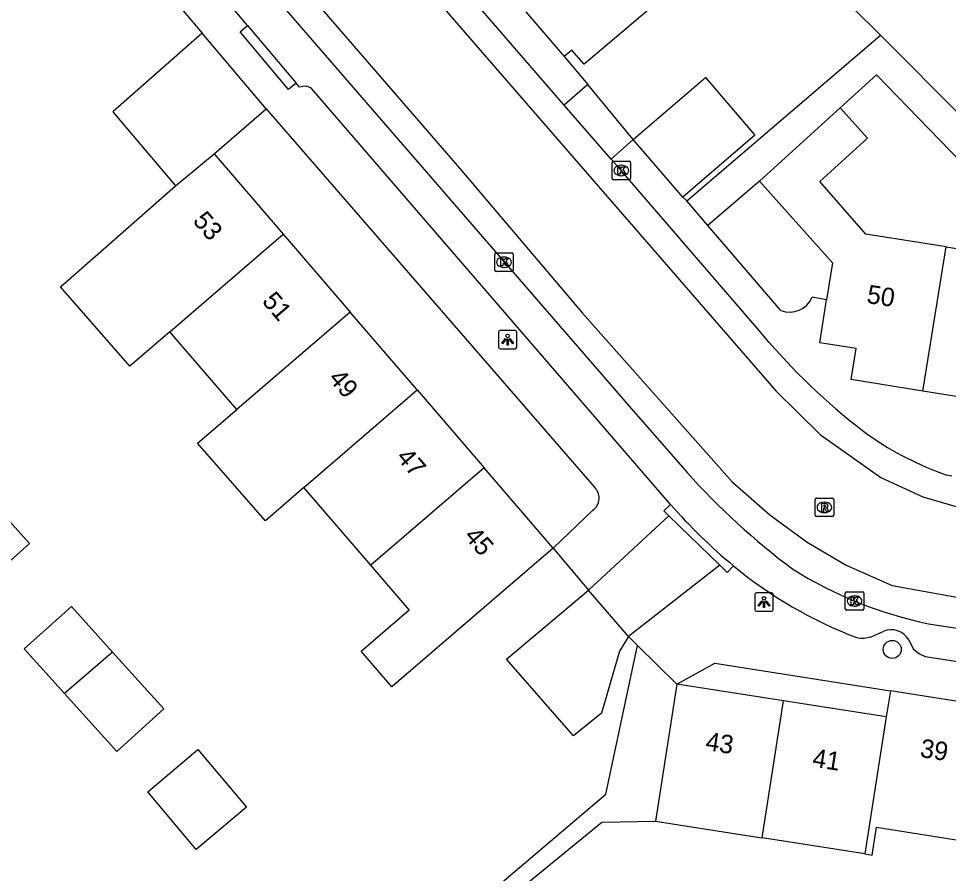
# Model space of a CAD drawing. Extents: x 162172 to 163187, y 382874 to 383684.
# Drawn here: x 162523.1 to 162573.4, y 383322.9 to 383369.1 of the extents above; entities that cross this region are included whole.
import ezdxf

# ---------------------------------------------------------------- set-up
doc = ezdxf.new("R2010")
doc.units = 0
for name, color, linetype in [('IMGEO_Boom', 7, 'Continuous'), ('IMGEO_Kolk', 7, 'Continuous'), ('IMGEO_Lichtpunt', 7, 'Continuous'), ('IMGEO_Pand', 7, 'Continuous'), ('IMGEO_Pand_nummerreeks', 7, 'Continuous'), ('IMGEO_Rijbaan_lokaal_gesloten', 7, 'Continuous'), ('IMGEO_Rijbaan_lokaal_open', 7, 'Continuous'), ('IMGEO_Rioolput', 7, 'Continuous'), ('IMGEO_Voetpad_open', 7, 'Continuous')]:
    doc.layers.add(name, color=color, linetype=linetype)

msp = doc.modelspace()

# ---------------------------------------------------------------- linework, layer by layer
at = {"layer": 'IMGEO_Boom'}
msp.add_circle((162570.37, 383334.962), 0.489, dxfattribs=at)
at = {"layer": 'IMGEO_Kolk'}
for p, q in [((162555.215, 383360.44), (162555.215, 383361.292)), ((162555.29, 383361.366), (162556.142, 383361.366)), ((162555.703, 383361.146), (162555.728, 383361.146)), ((162556.216, 383361.292), (162556.216, 383360.44)), ((162556.142, 383360.366), (162555.29, 383360.366)), ((162555.726, 383360.586), (162555.701, 383360.586)), ((162548.874, 383355.482), (162548.874, 383356.334)), ((162548.949, 383356.408), (162549.801, 383356.408)), ((162549.362, 383356.188), (162549.387, 383356.188)), ((162549.875, 383356.334), (162549.875, 383355.482)), ((162549.385, 383355.628), (162549.36, 383355.628)), ((162549.801, 383355.408), (162548.949, 383355.408)), ((162567.831, 383337.157), (162567.831, 383338.009)), ((162567.906, 383338.083), (162568.758, 383338.083)), ((162568.832, 383338.009), (162568.832, 383337.157)), ((162568.319, 383337.863), (162568.344, 383337.863)), ((162568.758, 383337.083), (162567.906, 383337.083)), ((162568.342, 383337.303), (162568.317, 383337.303))]:
    msp.add_line(p, q, dxfattribs=at)
for points in [[(162555.215, 383360.44), (162555.215, 383361.292)], [(162555.29, 383361.366), (162556.142, 383361.366)], [(162556.216, 383361.292), (162556.216, 383360.44)], [(162555.536, 383361.066), (162555.659, 383361.066), (162555.659, 383360.915), (162555.789, 383361.066), (162555.953, 383361.066), (162555.807, 383360.915), (162555.96, 383360.666), (162555.808, 383360.666), (162555.723, 383360.83), (162555.659, 383360.763), (162555.659, 383360.666), (162555.536, 383360.666), (162555.536, 383361.066)], [(162556.142, 383360.366), (162555.29, 383360.366)], [(162548.874, 383355.482), (162548.874, 383356.334)], [(162548.949, 383356.408), (162549.801, 383356.408)], [(162549.195, 383356.108), (162549.318, 383356.108), (162549.318, 383355.957), (162549.448, 383356.108), (162549.612, 383356.108), (162549.466, 383355.957), (162549.619, 383355.708), (162549.467, 383355.708), (162549.382, 383355.872), (162549.318, 383355.805), (162549.318, 383355.708), (162549.195, 383355.708), (162549.195, 383356.108)], [(162549.875, 383356.334), (162549.875, 383355.482)], [(162549.801, 383355.408), (162548.949, 383355.408)], [(162567.831, 383337.157), (162567.831, 383338.009)], [(162567.906, 383338.083), (162568.758, 383338.083)], [(162568.832, 383338.009), (162568.832, 383337.157)], [(162568.152, 383337.783), (162568.275, 383337.783), (162568.275, 383337.632), (162568.405, 383337.783), (162568.569, 383337.783), (162568.423, 383337.632), (162568.576, 383337.383), (162568.424, 383337.383), (162568.339, 383337.547), (162568.275, 383337.48), (162568.275, 383337.383), (162568.152, 383337.383), (162568.152, 383337.783)], [(162568.758, 383337.083), (162567.906, 383337.083)]]:
    msp.add_lwpolyline(points, dxfattribs=at)
for centre, start, end in [((162555.292, 383361.29), 91.552, 178.448), ((162555.292, 383361.29), 91.552, 178.448), ((162556.14, 383361.29), 1.552, 88.448), ((162556.14, 383361.29), 1.552, 88.448), ((162555.292, 383360.442), 181.552, 268.448), ((162555.292, 383360.442), 181.552, 268.448), ((162556.14, 383360.442), 271.552, 358.448), ((162556.14, 383360.442), 271.552, 358.448), ((162548.951, 383356.332), 91.552, 178.448), ((162548.951, 383356.332), 91.552, 178.448), ((162549.799, 383356.332), 1.552, 88.448), ((162549.799, 383356.332), 1.552, 88.448), ((162548.951, 383355.484), 181.552, 268.448), ((162548.951, 383355.484), 181.552, 268.448), ((162549.799, 383355.484), 271.552, 358.448), ((162549.799, 383355.484), 271.552, 358.448), ((162567.908, 383338.007), 91.552, 178.448), ((162567.908, 383338.007), 91.552, 178.448), ((162568.756, 383338.007), 1.552, 88.448), ((162568.756, 383338.007), 1.552, 88.448), ((162567.908, 383337.159), 181.552, 268.448), ((162567.908, 383337.159), 181.552, 268.448), ((162568.756, 383337.159), 271.552, 358.448), ((162568.756, 383337.159), 271.552, 358.448)]:
    msp.add_arc(centre, 0.0765, start, end, dxfattribs=at)
for centre, major_axis, ratio, start_param, end_param in [((162555.702, 383360.866), (-0.387, 0.002), 0.722429, 4.712389, 7.853982), ((162555.727, 383360.866), (-0.39, 0.002), 0.717154, 1.570796, 4.712389), ((162549.361, 383355.908), (-0.387, 0.002), 0.722429, 4.712389, 7.853982), ((162549.386, 383355.908), (-0.39, 0.002), 0.717154, 1.570796, 4.712389), ((162568.318, 383337.583), (-0.387, 0.002), 0.722429, 4.712389, 7.853982), ((162568.343, 383337.583), (-0.39, 0.002), 0.717154, 1.570796, 4.712389)]:
    msp.add_ellipse(centre, major_axis=major_axis, ratio=ratio, start_param=start_param, end_param=end_param, dxfattribs=at)
at = {"layer": 'IMGEO_Lichtpunt'}
for p, q in [((162549.071, 383352.125), (162549.071, 383351.318)), ((162549.071, 383352.125), (162549.071, 383351.318)), ((162549.973, 383352.22), (162549.165, 383352.22)), ((162549.973, 383352.22), (162549.165, 383352.22)), ((162550.067, 383351.318), (162550.067, 383352.125)), ((162550.067, 383351.318), (162550.067, 383352.125)), ((162549.165, 383351.224), (162549.973, 383351.224)), ((162549.165, 383351.224), (162549.973, 383351.224)), ((162563.84, 383338.025), (162563.032, 383338.025)), ((162563.84, 383338.025), (162563.032, 383338.025)), ((162562.938, 383337.93), (162562.938, 383337.123)), ((162562.938, 383337.93), (162562.938, 383337.123)), ((162563.934, 383337.123), (162563.934, 383337.93)), ((162563.934, 383337.123), (162563.934, 383337.93)), ((162563.032, 383337.029), (162563.84, 383337.029)), ((162563.032, 383337.029), (162563.84, 383337.029))]:
    msp.add_line(p, q, dxfattribs=at)
for points in [[(162549.445, 383351.789), (162549.484, 383351.761), (162549.296, 383351.499), (162549.258, 383351.526), (162549.445, 383351.789)], [(162549.547, 383351.741), (162549.594, 383351.741), (162549.594, 383351.419), (162549.547, 383351.419), (162549.547, 383351.741)], [(162549.657, 383351.761), (162549.695, 383351.788), (162549.882, 383351.526), (162549.843, 383351.498), (162549.657, 383351.761)], [(162563.312, 383337.594), (162563.351, 383337.566), (162563.163, 383337.304), (162563.125, 383337.331), (162563.312, 383337.594)], [(162563.414, 383337.546), (162563.461, 383337.546), (162563.461, 383337.224), (162563.414, 383337.224), (162563.414, 383337.546)], [(162563.524, 383337.566), (162563.562, 383337.593), (162563.749, 383337.331), (162563.71, 383337.303), (162563.524, 383337.566)]]:
    msp.add_lwpolyline(points, dxfattribs=at)
for centre in [(162549.57, 383351.923), (162563.437, 383337.728)]:
    msp.add_circle(centre, 0.0994, dxfattribs=at)
for centre, start, end in [((162549.165, 383352.125), 90, 180), ((162549.165, 383352.125), 90, 180), ((162549.973, 383352.125), 0, 90), ((162549.973, 383352.125), 0, 90), ((162549.165, 383351.318), 180, 270), ((162549.165, 383351.318), 180, 270), ((162549.973, 383351.318), 270, 0), ((162549.973, 383351.318), 270, 360), ((162563.032, 383337.93), 90, 180), ((162563.032, 383337.93), 90, 180), ((162563.84, 383337.93), 0, 90), ((162563.84, 383337.93), 0, 90), ((162563.032, 383337.123), 180, 270), ((162563.032, 383337.123), 180, 270), ((162563.84, 383337.123), 270, 0), ((162563.84, 383337.123), 270, 360)]:
    msp.add_arc(centre, 0.0946, start, end, dxfattribs=at)
at = {"layer": 'IMGEO_Pand'}
for points in [[(162559.112, 383379.328), (162556.099, 383376.772), (162560.11, 383372.044), (162553.704, 383366.609), (162553.038, 383367.382), (162552.635, 383367.035)], [(162550.557, 383369.452), (162552.635, 383367.035)], [(162533.053, 383368.288), (162528.208, 383364.045), (162531.601, 383360.031)], [(162536.515, 383364.193), (162533.053, 383368.288)], [(162556.365, 383362.547), (162560.263, 383365.898), (162562.943, 383362.781), (162559.045, 383359.429)], [(162533.692, 383361.764), (162536.515, 383364.193)], [(162567.562, 383364.252), (162563.192, 383360.287)], [(162573.297, 383356.738), (162568.949, 383357.426), (162566.45, 383360.271), (162569.041, 383362.623), (162567.562, 383364.252)], [(162559.045, 383359.429), (162556.365, 383362.547)], [(162531.601, 383360.031), (162533.692, 383361.764)], [(162533.692, 383361.764), (162537.428, 383357.422)], [(162563.192, 383360.287), (162567.133, 383355.865), (162566.817, 383353.869)], [(162531.298, 383352.148), (162529.139, 383350.291), (162525.381, 383354.579), (162527.562, 383356.491), (162531.601, 383360.031)], [(162531.298, 383352.148), (162537.428, 383357.422)], [(162537.428, 383357.422), (162541.049, 383353.211)], [(162572.018, 383348.939), (162573.297, 383356.738)], [(162573.297, 383356.738), (162578.97, 383355.84)], [(162572.018, 383348.939), (162568.152, 383349.554), (162568.419, 383351.241), (162566.45, 383351.553), (162566.817, 383353.869)], [(162541.049, 383353.211), (162534.92, 383347.938)], [(162544.672, 383349.001), (162541.049, 383353.211)], [(162534.92, 383347.938), (162531.298, 383352.148)], [(162538.542, 383343.728), (162544.672, 383349.001)], [(162544.672, 383349.001), (162548.294, 383344.79)], [(162577.691, 383348.037), (162572.018, 383348.939)], [(162538.542, 383343.728), (162536.477, 383341.918), (162532.8, 383346.114), (162534.92, 383347.938)], [(162548.294, 383344.79), (162542.164, 383339.517)], [(162552.03, 383340.447), (162548.294, 383344.79)], [(162542.164, 383339.517), (162538.542, 383343.728)], [(162521.184, 383343.495), (162523.7, 383340.699), (162521.742, 383338.937), (162519.187, 383341.776)], [(162552.03, 383340.447), (162543.305, 383332.941), (162541.648, 383334.869), (162544.243, 383337.101), (162542.164, 383339.517)], [(162525.603, 383332.581), (162523.426, 383334.997), (162525.973, 383337.292), (162528.203, 383334.818)], [(162528.203, 383334.818), (162530.972, 383331.745), (162528.425, 383329.45), (162525.603, 383332.581)], [(162528.203, 383334.818), (162525.603, 383332.581)], [(162558.721, 383333.081), (162557.567, 383325.671)], [(162564.496, 383332.182), (162558.721, 383333.081)], [(162570.27, 383332.718), (162570.052, 383331.317)], [(162576, 383331.826), (162570.27, 383332.718)], [(162563.343, 383324.772), (162564.496, 383332.182)], [(162570.052, 383331.317), (162564.496, 383332.182)], [(162570.052, 383331.317), (162568.897, 383323.907)], [(162530.1, 383327.263), (162532.82, 383329.55), (162535.439, 383326.434), (162532.719, 383324.147), (162530.1, 383327.263)], [(162557.567, 383325.671), (162562.508, 383324.902), (162563.343, 383324.772)], [(162568.897, 383323.907), (162569.289, 383323.846), (162569.522, 383325.347), (162574.859, 383324.497)], [(162568.897, 383323.907), (162563.343, 383324.772)]]:
    msp.add_lwpolyline(points, dxfattribs=at)
at = {"layer": 'IMGEO_Rijbaan_lokaal_gesloten'}
for points in [[(162529.068, 383389.331), (162532.979, 383384.867), (162547.857, 383367.645), (162564.078, 383348.944), (162566.493, 383346.567), (162567.778, 383345.671), (162569.764, 383344.268), (162572.023, 383343.216), (162574.438, 383342.515), (162592.762, 383339.748), (162610.619, 383337.021), (162627.21, 383334.45), (162667.305, 383328.139)], [(162525.302, 383386.015), (162530.019, 383380.581), (162547.078, 383360.866), (162553.621, 383353.151), (162561.721, 383344.034), (162563.747, 383342.242), (162565.772, 383340.762), (162567.875, 383339.515), (162570.367, 383338.424), (162578.157, 383337.021), (162597.474, 383334.138), (162623.802, 383330.008), (162643.197, 383327.047), (162662.339, 383324.046)], [(162524.132, 383384.985), (162526.275, 383382.59), (162530.552, 383377.712), (162533.37, 383374.43), (162533.509, 383374.259), (162556.137, 383348.129), (162559.274, 383344.525)], [(162552.634, 383364.406), (162542.748, 383375.831)], [(162555.161, 383361.47), (162552.634, 383364.406)], [(162563.724, 383351.569), (162563.062, 383352.332), (162555.711, 383360.865), (162555.161, 383361.47)], [(162573.598, 383344.329), (162573.305, 383344.396)], [(162572.334, 383336.354), (162582.593, 383334.79), (162596.519, 383332.638), (162599.695, 383332.15)]]:
    msp.add_lwpolyline(points, dxfattribs=at)
for centre, radius, start, end in [((162589.017, 383373.274), 33.329, 220.6344, 233.3676), ((162579.198, 383361.09), 17.703, 235.3401, 250.5569), ((162589.069, 383371.413), 40.133, 222.0642, 233.1091), ((162576.854, 383358.205), 22.314, 237.8406, 258.3124)]:
    msp.add_arc(centre, radius, start, end, dxfattribs=at)
at = {"layer": 'IMGEO_Rijbaan_lokaal_open'}
for points in [[(162559.112, 383379.328), (162566.716, 383371.198), (162569.735, 383368.176)], [(162569.735, 383368.176), (162574.27, 383363.636), (162574.756, 383363.046), (162575.389, 383363.568), (162578.52, 383366.243)], [(162556.113, 383335.67), (162555.613, 383334.876), (162554.651, 383331.524), (162553.124, 383330.286), (162549.506, 383334.442), (162553.936, 383338.173)], [(162556.113, 383335.67), (162553.936, 383338.173)]]:
    msp.add_lwpolyline(points, dxfattribs=at)
at = {"layer": 'IMGEO_Rioolput'}
for p, q in [((162566.204, 383342.222), (162566.204, 383343.074)), ((162566.279, 383343.148), (162567.131, 383343.148)), ((162567.205, 383343.074), (162567.205, 383342.222)), ((162566.692, 383342.928), (162566.717, 383342.928)), ((162567.131, 383342.148), (162566.279, 383342.148)), ((162566.715, 383342.368), (162566.69, 383342.368))]:
    msp.add_line(p, q, dxfattribs=at)
for points in [[(162566.204, 383342.222), (162566.204, 383343.074)], [(162566.279, 383343.148), (162567.131, 383343.148)], [(162567.205, 383343.074), (162567.205, 383342.222)], [(162566.793, 383342.846), (162566.541, 383342.848), (162566.541, 383342.448)], [(162566.541, 383342.448), (162566.665, 383342.448), (162566.665, 383342.61), (162566.676, 383342.61)], [(162566.719, 383342.767), (162566.665, 383342.767), (162566.665, 383342.686)], [(162566.665, 383342.686), (162566.717, 383342.686)], [(162566.723, 383342.581), (162566.794, 383342.448), (162566.934, 383342.448), (162566.869, 383342.574)], [(162567.131, 383342.148), (162566.279, 383342.148)]]:
    msp.add_lwpolyline(points, dxfattribs=at)
for centre, radius, start, end in [((162566.281, 383343.072), 0.0765, 91.552, 178.448), ((162566.281, 383343.072), 0.0765, 91.552, 178.448), ((162567.129, 383343.072), 0.0765, 1.552, 88.448), ((162567.129, 383343.072), 0.0765, 1.552, 88.448), ((162566.675, 383342.557), 0.0533, 26.0293, 88.6989), ((162566.701, 383342.875), 0.19, 274.7715, 282.9687), ((162566.725, 383342.671), 0.0964, 77.0061, 93.1865), ((162566.739, 383342.728), 0.0378, 276.6634, 79.6772), ((162566.792, 383342.736), 0.109, 350.3612, 89.416), ((162566.79, 383342.736), 0.112, 277.5842, 350.9817), ((162566.774, 383342.521), 0.108, 29.5134, 73.7905), ((162566.281, 383342.224), 0.0765, 181.552, 268.448), ((162566.281, 383342.224), 0.0765, 181.552, 268.448), ((162567.129, 383342.224), 0.0765, 271.552, 358.448), ((162567.129, 383342.224), 0.0765, 271.552, 358.448)]:
    msp.add_arc(centre, radius, start, end, dxfattribs=at)
for centre, major_axis, ratio, start_param, end_param in [((162566.691, 383342.648), (-0.387, 0.002), 0.722429, 4.712389, 7.853982), ((162566.716, 383342.648), (-0.39, 0.002), 0.717154, 1.570796, 4.712389)]:
    msp.add_ellipse(centre, major_axis=major_axis, ratio=ratio, start_param=start_param, end_param=end_param, dxfattribs=at)
at = {"layer": 'IMGEO_Voetpad_open'}
for points in [[(162528.873, 383373.233), (162533.053, 383368.288)], [(162535.503, 383368.71), (162533.366, 383371.252)], [(162538.127, 383365.59), (162537.719, 383365.247), (162535.096, 383368.368), (162535.503, 383368.71)], [(162535.503, 383368.71), (162538.127, 383365.59)], [(162559.261, 383359.225), (162569.735, 383368.176)], [(162552.635, 383367.035), (162553.909, 383365.522)], [(162567.562, 383364.252), (162569.514, 383366.031), (162574.642, 383360.756), (162579.85, 383365.046)], [(162538.316, 383365.365), (162538.127, 383365.59)], [(162558.37, 383342.809), (162543.287, 383360.29), (162538.973, 383365.28)], [(162553.909, 383365.522), (162552.634, 383364.406)], [(162556.365, 383362.547), (162553.909, 383365.522)], [(162536.515, 383364.193), (162554.253, 383343.752)], [(162556.365, 383362.547), (162555.161, 383361.47)], [(162563.192, 383360.287), (162560.402, 383357.895)], [(162559.261, 383359.225), (162559.045, 383359.429)], [(162560.402, 383357.895), (162559.261, 383359.225)], [(162564.338, 383353.303), (162560.402, 383357.895)], [(162566.817, 383353.869), (162566.042, 383354.011)], [(162558.288, 383342.193), (162558.022, 383342.451), (162558.37, 383342.809)], [(162554.184, 383342.492), (162552.03, 383340.447)], [(162553.936, 383338.173), (162558.288, 383342.193)], [(162558.288, 383342.193), (162561.038, 383339.521)], [(162552.03, 383340.447), (162553.936, 383338.173)], [(162561.038, 383339.521), (162556.113, 383335.67)], [(162561.79, 383339.486), (162561.442, 383339.128), (162561.038, 383339.521)], [(162556.601, 383335.185), (162556.113, 383335.67)], [(162569.224, 383335.654), (162569.884, 383335.942)], [(162571.261, 383335.487), (162571.511, 383334.993), (162571.813, 383334.744), (162572.148, 383334.573), (162583.064, 383332.902)], [(162554.081, 383310.226), (162545.772, 383319.408), (162554.885, 383327.131), (162556.601, 383335.185)], [(162558.721, 383333.081), (162556.601, 383335.185)], [(162558.721, 383333.081), (162560.782, 383334.228), (162570.27, 383332.718)], [(162548.001, 383319.612), (162547.729, 383319.944), (162554.656, 383325.625), (162557.567, 383325.671)]]:
    msp.add_lwpolyline(points, dxfattribs=at)
for centre, radius, start, end in [((162538.576, 383364.793), 0.629, 50.8361, 114.4204), ((162564.833, 383354.515), 1.31, 247.7754, 337.3497), ((162553.706, 383343.15), 0.814, 306.0162, 47.7148), ((162581.028, 383362.707), 30.155, 221.2893, 230.359), ((162576.69, 383357.405), 23.305, 230.2555, 249.3193), ((162570.313, 383334.931), 1.099, 30.4222, 113.0078), ((162568.752, 383336.952), 1.381, 257.795, 289.9924)]:
    msp.add_arc(centre, radius, start, end, dxfattribs=at)

# ---------------------------------------------------------------- texts
at = {"layer": 'IMGEO_Pand_nummerreeks'}
for s, rotation, p in [('53', 310.7038, (162532.5, 383358.12)), ('50', 350.996, (162568.954, 383353.708)), ('51', 310.7038, (162536.242, 383353.771)), ('49', 310.7038, (162539.836, 383349.593)), ('47', 310.7038, (162543.503, 383345.33)), ('45', 310.7038, (162547.171, 383341.066)), ('43', 351.1513, (162560.233, 383329.527)), ('39', 351.1475, (162571.836, 383329.155)), ('41', 351.1513, (162566.009, 383328.627))]:
    msp.add_text(s, height=1, rotation=rotation, dxfattribs=at).set_placement(p)

doc.saveas('drawing.dxf')
